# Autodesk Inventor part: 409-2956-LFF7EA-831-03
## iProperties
Created: 2010-09
Part Number: 409-2956-LFF7EA-831-03
Material: 3/8" OD TUBE - SS
Document SubType Name: Modeling
Designer: S. Boerckel
Engineer: Steve Boerckel
Mass: 61.6007 g
Surface Area: 127.01 cm^2
Volume: 7.62385 cm^3
Density: 8.08 g/cm^3
Description: LOW PRESSURE GAUGE TUBE
LGTH: 2.820 in
Author: S. Boerckel
Revision Number: 0
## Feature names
1. Sweep3
